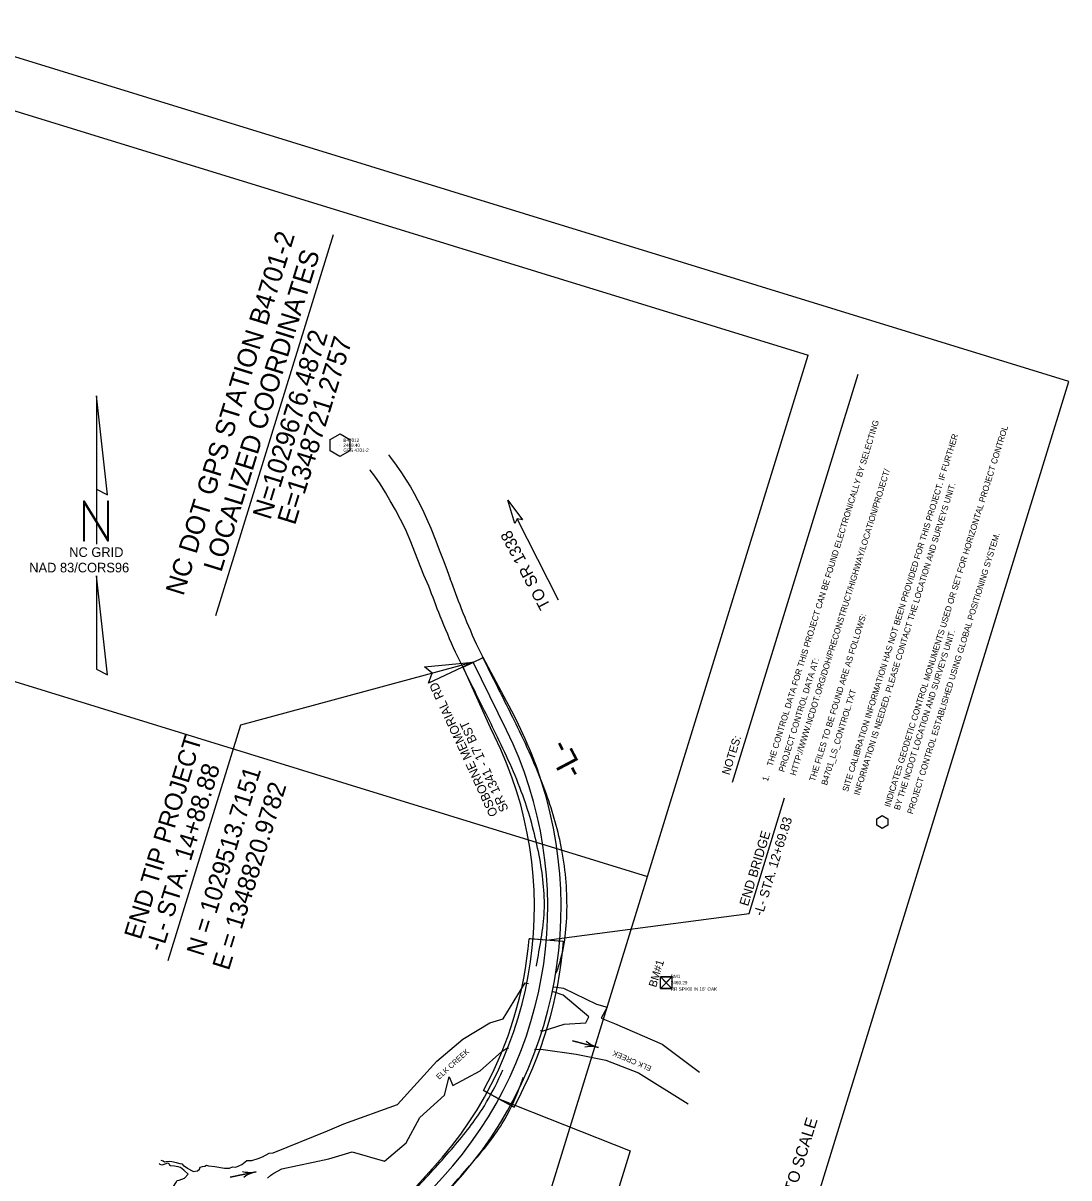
# Model space of a CAD drawing. Extents: x 1348011 to 1349268, y 1028333 to 1030014.
# Drawn here: x 1348484 to 1349268, y 1029127 to 1029993 of the extents above; entities that cross this region are included whole.
import ezdxf

# ---------------------------------------------------------------- set-up
doc = ezdxf.new("R2010")
doc.units = 0
for name, color, linetype in [('CTL Bench Mark CELL', 7, 'Continuous'), ('CTL Bench Mark Cogo Comment', 7, 'Continuous'), ('CTL Bench Mark Cogo Elevation', 7, 'Continuous'), ('CTL Bench Mark Cogo Number', 7, 'Continuous'), ('CTL Bench Mark Text', 7, 'Continuous'), ('CTL GPS Vertical CELL', 7, 'Continuous'), ('CTL GPS Vertical Cogo Comment', 7, 'Continuous'), ('CTL GPS Vertical Cogo Elevation', 7, 'Continuous'), ('CTL GPS Vertical Cogo Number', 7, 'Continuous'), ('CTL North Arrow NAD 83 NSRS 2007 CELL', 7, 'Continuous'), ('CTL Sheet Border CELL', 7, 'Continuous'), ('CTL Sheet Notes CELL', 7, 'Continuous'), ('Default', 7, 'Continuous'), ('Exist Hydro River Flow Arrow CELL', 7, 'Continuous'), ('Exist Hydro Stream or Body of Water', 7, 'Continuous'), ('Exist Hydro Stream or Body of Water Text', 7, 'Continuous'), ('Exist Roads EOP', 7, 'Continuous'), ('Prop Horizontal Alignment', 7, 'Continuous'), ('Prop Horizontal Alignment Station Label', 7, 'Continuous'), ('Prop Leader Line Light', 7, 'Continuous'), ('Prop Leader Line Medium', 7, 'Continuous'), ('Prop Roadway Bridge', 7, 'Continuous'), ('Prop Shade Medium', 7, 'Continuous'), ('Prop Terminator CELL', 7, 'Continuous'), ('Scratch_Level_3', 7, 'Continuous'), ('Sheet Data Field CELL', 7, 'Continuous'), ('Sheet Symbology CELL', 7, 'Continuous')]:
    doc.layers.add(name, color=color, linetype=linetype)

msp = doc.modelspace()

# ---------------------------------------------------------------- linework, layer by layer
at = {"layer": 'CTL Bench Mark CELL'}
msp.add_line((1348965.75, 1029273.43), (1348965.75, 1029273.43), dxfattribs=at)
msp.add_lwpolyline([(1348961.43, 1029277.74), (1348970.06, 1029277.74), (1348970.06, 1029269.11), (1348961.43, 1029269.11)], close=True, dxfattribs=at)
for points in [[(1348970.06, 1029277.74), (1348961.43, 1029269.11), (1348965.74, 1029273.42), (1348970.06, 1029269.11), (1348961.43, 1029277.74)], [(1348965.74, 1029273.42), (1348970.06, 1029277.74), (1348961.43, 1029277.74), (1348965.74, 1029273.42)], [(1348965.74, 1029273.42), (1348961.43, 1029269.11), (1348970.06, 1029269.11), (1348965.74, 1029273.42)]]:
    msp.add_lwpolyline(points, dxfattribs=at)
at = {"layer": 'CTL GPS Vertical CELL'}
for p, q in [((1348721.24, 1029676.49), (1348721.24, 1029676.49)), ((1349127.83, 1029393.95), (1349127.83, 1029393.95))]:
    msp.add_line(p, q, dxfattribs=at)
for points in [[(1348713.88, 1029680.76), (1348721.29, 1029684.89), (1348728.7, 1029680.81), (1348728.58, 1029672.32), (1348721.17, 1029668.02), (1348713.88, 1029672.15)], [(1349123.64, 1029396.37), (1349127.85, 1029398.72), (1349132.06, 1029396.41), (1349132, 1029391.58), (1349127.79, 1029389.14), (1349123.64, 1029391.49)]]:
    msp.add_lwpolyline(points, close=True, dxfattribs=at)
at = {"layer": 'CTL North Arrow NAD 83 NSRS 2007 CELL'}
msp.add_line((1348538.91, 1029608.7), (1348538.91, 1029608.7), dxfattribs=at)
for points in [[(1348538.73, 1029713.44), (1348538.73, 1029643.45), (1348546.98, 1029639.33)], [(1348528.86, 1029604.78), (1348529.68, 1029604.78), (1348529.68, 1029632.77), (1348546.98, 1029604.78), (1348547.8, 1029604.78), (1348547.8, 1029634.41), (1348546.98, 1029634.41), (1348546.98, 1029606.42), (1348529.68, 1029634.41), (1348528.86, 1029634.41)], [(1348538.73, 1029508.44), (1348546.98, 1029504.34), (1348538.73, 1029578.43)]]:
    msp.add_lwpolyline(points, close=True, dxfattribs=at)
msp.add_lwpolyline([(1348538.73, 1029643.45), (1348538.73, 1029602.29)], dxfattribs=at)
at = {"layer": 'CTL Sheet Border CELL'}
msp.add_lwpolyline([(1348395.15, 1029993.01), (1348011.26, 1028746.43), (1348883.85, 1028477.71), (1349267.74, 1029724.29)], close=True, dxfattribs=at)
at = {"layer": 'CTL Sheet Notes CELL'}
msp.add_line((1349015.42, 1029423.77), (1349109.8, 1029729.66), dxfattribs=at)
at = {"layer": 'Default'}
for p, q in [((1348813.47, 1029510.02), (1348828.47, 1029517.41)), ((1348834.1, 1029464.45), (1348813.47, 1029510.02)), ((1348852.05, 1029473.29), (1348828.47, 1029517.41)), ((1348855.06, 1029467.16), (1348852.05, 1029473.29)), ((1348837.12, 1029458.33), (1348834.1, 1029464.45)), ((1348775.79, 1029117.88), (1348790.71, 1029134.15))]:
    msp.add_line(p, q, dxfattribs=at)
for radius in [310, 290]:
    msp.add_arc((1348576.98, 1029330.16), radius, 317.47773, 26.22881, dxfattribs=at)
at = {"layer": 'Exist Hydro River Flow Arrow CELL'}
for p, q in [((1348905.32, 1029227.31), (1348905.32, 1029227.31)), ((1348648.55, 1029129.62), (1348648.55, 1029129.62))]:
    msp.add_line(p, q, dxfattribs=at)
for points in [[(1348905.87, 1029229.53), (1348907.51, 1029228.31), (1348909.27, 1029227.21), (1348911.14, 1029226.26), (1348913.05, 1029225.46), (1348915.02, 1029224.89), (1348895.61, 1029229.73), (1348915.02, 1029224.89), (1348913.01, 1029225.31), (1348910.95, 1029225.51), (1348908.86, 1029225.54), (1348906.79, 1029225.4), (1348904.76, 1029225.09)], [(1348648.07, 1029131.85), (1348650.08, 1029131.48), (1348652.14, 1029131.27), (1348654.24, 1029131.24), (1348656.31, 1029131.36), (1348658.33, 1029131.72), (1348638.78, 1029127.51), (1348658.33, 1029131.72), (1348656.34, 1029131.22), (1348654.4, 1029130.48), (1348652.51, 1029129.59), (1348650.71, 1029128.55), (1348649.03, 1029127.38)]]:
    msp.add_lwpolyline(points, dxfattribs=at)
at = {"layer": 'Exist Hydro Stream or Body of Water'}
for points in [[(1348671.04, 1029145.85), (1348711.91, 1029162.47), (1348724.23, 1029167.73), (1348764.36, 1029182.18), (1348793.73, 1029214.59), (1348813.44, 1029231.21), (1348833.67, 1029243.41), (1348843.53, 1029246.37), (1348860.07, 1029273.27), (1348862.58, 1029272.92)], [(1348871.41, 1029237.6), (1348872.86, 1029237.11), (1348889.42, 1029242.41), (1348905.56, 1029243.38), (1348907.78, 1029247.78), (1348888.56, 1029264.14), (1348881.39, 1029266.69), (1348880.38, 1029266.29)], [(1348881.62, 1029270.25), (1348888.82, 1029269.24), (1348913.56, 1029257.38), (1348921.57, 1029255.16), (1348917.15, 1029246.84), (1348926.96, 1029242.82), (1348962.79, 1029227.39), (1348990.8, 1029206.3)], [(1348677.73, 1029133.76), (1348712.96, 1029141.41), (1348730.43, 1029146.71), (1348754.5, 1029139.72), (1348770.92, 1029153.32), (1348781.06, 1029172.35), (1348799.58, 1029188.98), (1348803.07, 1029202.76), (1348805.79, 1029196.31), (1348826.35, 1029207.46), (1348842.47, 1029221.94), (1348846.45, 1029224.45), (1348847.5, 1029224.4)], [(1348867.03, 1029223.6), (1348873.62, 1029223.33), (1348898.36, 1029219.75), (1348920.53, 1029215.34), (1348945.09, 1029205.74), (1348982.2, 1029182.64)], [(1348659.88, 1029141.67), (1348663.08, 1029142.95), (1348668.16, 1029145.64)], [(1348668.16, 1029145.64), (1348671.04, 1029145.85)], [(1348607.36, 1029129.9), (1348604.2, 1029132.95), (1348601.62, 1029134.74), (1348599.8, 1029135.25), (1348598.38, 1029135.69), (1348597.2, 1029135.92), (1348594.23, 1029136.02), (1348593.83, 1029136.37), (1348593.33, 1029137.1), (1348593.05, 1029137.51), (1348592.71, 1029137.92), (1348591.76, 1029138), (1348590.55, 1029137.59), (1348589.28, 1029137.07), (1348587.79, 1029136.63), (1348586.54, 1029137.04), (1348585.68, 1029137.74)], [(1348611.1, 1029131.84), (1348607.01, 1029134), (1348604.42, 1029135.94), (1348603.11, 1029137.25), (1348601.52, 1029137.51), (1348598.68, 1029138.39), (1348595.23, 1029139.1), (1348593.3, 1029139.32), (1348590.8, 1029139.09), (1348589.74, 1029138.98), (1348588.76, 1029139.5), (1348587.26, 1029140.22)], [(1348611.1, 1029131.84), (1348614.45, 1029132.4), (1348615.95, 1029133.55), (1348616.53, 1029135.05), (1348618.24, 1029135.49), (1348620.03, 1029135.77), (1348621.23, 1029136.6), (1348622.59, 1029136.22), (1348627.39, 1029135.64), (1348634.69, 1029134.3), (1348638.31, 1029134.32), (1348640.69, 1029135.47), (1348643.26, 1029135.23), (1348647.66, 1029137.1), (1348651.28, 1029140), (1348655.2, 1029140.13), (1348659.88, 1029141.67)], [(1348596.35, 1029120.56), (1348598.13, 1029123.25), (1348599.17, 1029125.06), (1348600.62, 1029125.28), (1348604.69, 1029126.88), (1348607.36, 1029129.9)], [(1348666.96, 1029126.75), (1348669.41, 1029129.16), (1348671.69, 1029130.65), (1348677.73, 1029133.76)]]:
    msp.add_lwpolyline(points, dxfattribs=at)
at = {"layer": 'Exist Roads EOP'}
for p, q in [((1348843.08, 1029207.34), (1348843.41, 1029208.1)), ((1348858.38, 1029201.61), (1348858.75, 1029202.41))]:
    msp.add_line(p, q, dxfattribs=at)
for points in [[(1348757.58, 1029669.32), (1348759.23, 1029667.29), (1348763.43, 1029661.47), (1348767.37, 1029655.84), (1348770.81, 1029650.35), (1348774, 1029645.31), (1348776.86, 1029640.16), (1348779.54, 1029635.14), (1348781.9, 1029630.7), (1348784.11, 1029626.15), (1348786.07, 1029621.65), (1348789.36, 1029614.22), (1348792.6, 1029606.07), (1348796.18, 1029596.87), (1348796.67, 1029595.55)], [(1348787.85, 1029570.74), (1348784.22, 1029578.99), (1348777.31, 1029596.39), (1348774.32, 1029604.14), (1348770.36, 1029613.41), (1348766.73, 1029620.69), (1348762.8, 1029627.98), (1348758.96, 1029634.85), (1348755.29, 1029641.09), (1348751.31, 1029647.43), (1348747.35, 1029653.15), (1348743.79, 1029657.75), (1348743.62, 1029657.95)], [(1348796.67, 1029595.55), (1348798.99, 1029589.28), (1348801.58, 1029582.62), (1348803.95, 1029576.19)]]:
    msp.add_lwpolyline(points, dxfattribs=at)
for points in [[(1348819.76, 1029497.12), (1348807.96, 1029521.32), (1348796.41, 1029548.28), (1348787.85, 1029570.74)], [(1348835.36, 1029503.16), (1348823.68, 1029527.32), (1348812.34, 1029553.89), (1348803.95, 1029576.19)], [(1348883.28, 1029280.61), (1348883.52, 1029281.22), (1348891.35, 1029324.78), (1348887.59, 1029372.72), (1348875.98, 1029414.87), (1348854.37, 1029465.03), (1348835.36, 1029503.16)], [(1348868.46, 1029285.84), (1348868.57, 1029286.44), (1348874.38, 1029327), (1348870.51, 1029369.07), (1348859.35, 1029410.97), (1348839.31, 1029457.59), (1348819.76, 1029497.12)], [(1348777.13, 1029117.89), (1348804.82, 1029148.44), (1348827.72, 1029178.39), (1348840.41, 1029201.66), (1348843.08, 1029207.34)], [(1348790.41, 1029105.15), (1348818.4, 1029136.04), (1348842.84, 1029167.86), (1348855.87, 1029194.81), (1348858.38, 1029201.61)]]:
    msp.add_spline(points, degree=3, dxfattribs=at)
at = {"layer": 'Prop Horizontal Alignment'}
for p, q in [((1348846.09, 1029462.75), (1348820.98, 1029513.72)), ((1348749.37, 1029074.27), (1348798.08, 1029127.4))]:
    msp.add_line(p, q, dxfattribs=at)
msp.add_arc((1348576.98, 1029330.16), 300, 317.47773, 26.22881, dxfattribs=at)
at = {"layer": 'Prop Horizontal Alignment Station Label'}
msp.add_line((1348716.15, 1029834.23), (1348627.86, 1029548.54), dxfattribs=at)
at = {"layer": 'Prop Leader Line Medium'}
for p, q in [((1348820.98, 1029513.72), (1348646.58, 1029466.47)), ((1348646.58, 1029466.47), (1348592.15, 1029289.72)), ((1349027.91, 1029325.42), (1349054.57, 1029411.99)), ((1348875.95, 1029305.29), (1349027.91, 1029325.42)), ((1348840.31, 1029186.43), (1348938.84, 1029147.29)), ((1348938.84, 1029147.29), (1348911.11, 1029057.24))]:
    msp.add_line(p, q, dxfattribs=at)
at = {"layer": 'Prop Roadway Bridge'}
for p, q in [((1348888.9, 1029304.22), (1348862.99, 1029306.37)), ((1348851.72, 1029180.2), (1348828.89, 1029192.65)), ((1348829.77, 1029192.17), (1348850.84, 1029180.67))]:
    msp.add_line(p, q, dxfattribs=at)
for radius in [287, 313]:
    msp.add_arc((1348576.98, 1029330.16), radius, 331.37242, 355.24567, dxfattribs=at)
at = {"layer": 'Prop Shade Medium'}
for p, q in [((1348863.99, 1029306.29), (1348862.99, 1029306.37)), ((1348887.91, 1029304.3), (1348863.99, 1029306.29)), ((1348828.89, 1029192.65), (1348851.72, 1029180.2))]:
    msp.add_line(p, q, dxfattribs=at)
for radius in [287, 313]:
    msp.add_arc((1348576.98, 1029330.16), radius, 331.37242, 355.24567, dxfattribs=at)
at = {"layer": 'Prop Terminator CELL'}
for points in [[(1348852.35, 1029617.86), (1348846.99, 1029635.32), (1348858.02, 1029620.61), (1348854.12, 1029621.22)], [(1348784.6, 1029510.39), (1348820.98, 1029513.72), (1348787.67, 1029498.16), (1348790.45, 1029505.54)]]:
    msp.add_lwpolyline(points, close=True, dxfattribs=at)
at = {"layer": 'Scratch_Level_3'}
for p, q in [((1348428.33, 1029942.38), (1349072.16, 1029744.11)), ((1348951.78, 1029353.2), (1349072.16, 1029744.11)), ((1348307.95, 1029551.47), (1348951.78, 1029353.2)), ((1348831.4, 1028962.29), (1348951.78, 1029353.2))]:
    msp.add_line(p, q, dxfattribs=at)
at = {"layer": 'Sheet Symbology CELL'}
msp.add_line((1348885.06, 1029560.27), (1348854.08, 1029621.19), dxfattribs=at)

# ---------------------------------------------------------------- texts
at = {"layer": 'CTL Bench Mark Cogo Comment'}
msp.add_text('RR SPIKE IN 16" OAK', height=2.5, dxfattribs=at).set_placement((1348969.25, 1029267.43))
at = {"layer": 'CTL Bench Mark Cogo Elevation'}
msp.add_text('2469.29', height=2.5, dxfattribs=at).set_placement((1348969.25, 1029272.18))
at = {"layer": 'CTL Bench Mark Cogo Number'}
msp.add_text('BM1', height=2.5, dxfattribs=at).set_placement((1348969.25, 1029276.93))
at = {"layer": 'CTL Bench Mark Text'}
msp.add_text('BM#1', height=6, rotation=72.88344, dxfattribs=at).set_placement((1348958.19, 1029269.54))
at = {"layer": 'CTL GPS Vertical Cogo Comment'}
msp.add_text('GPS 4701-2', height=2.5, dxfattribs=at).set_placement((1348723.78, 1029671.49))
at = {"layer": 'CTL GPS Vertical Cogo Elevation'}
msp.add_text('2489.40', height=2.5, dxfattribs=at).set_placement((1348723.78, 1029675.24))
at = {"layer": 'CTL GPS Vertical Cogo Number'}
msp.add_text('B47012', height=2.5, dxfattribs=at).set_placement((1348723.78, 1029678.99))
at = {"layer": 'CTL North Arrow NAD 83 NSRS 2007 CELL'}
for s, p in [('NC GRID', (1348518.24, 1029592.69)), (' NAD 83/CORS96', (1348485.61, 1029581.12))]:
    msp.add_text(s, height=7.2, dxfattribs=at).set_placement(p)
at = {"layer": 'CTL Sheet Border CELL'}
msp.add_text('NOTE: DRAWING NOT TO SCALE', height=8.6957, rotation=72.77817, dxfattribs=at).set_placement((1349025.09, 1028995.35))
at = {"layer": 'CTL Sheet Notes CELL'}
for s, height, rotation, p in [('1.    THE CONTROL DATA FOR THIS PROJECT CAN BE FOUND ELECTRONICALLY BY SELECTING', 4.552, 72.85294, (1349042.02, 1029424.03)), ('SITE CALIBRATION INFORMATION HAS NOT BEEN PROVIDED FOR THIS PROJECT. IF FURTHER', 4.552, 72.85294, (1349102.09, 1029416.29)), ('INDICATES GEODETIC CONTROL MONUMENTS USED OR SET FOR HORIZONTAL PROJECT CONTROL', 4.552, 72.74769, (1349133.56, 1029404.82)), ('HTTP://WWW.NCDOT.ORG/DOH/PRECONSTRUCT/HIGHWAY/LOCATION/PROJECT/', 4.552, 72.85294, (1349062.89, 1029428.38)), ('INFORMATION IS NEEDED, PLEASE CONTACT THE LOCATION AND SURVEYS UNIT.', 4.552, 72.85294, (1349110.65, 1029413.65)), ('PROJECT CONTROL ESTABLISHED USING GLOBAL POSITIONING SYSTEM.', 4.552, 72.74769, (1349150.68, 1029399.5)), ('THE FILES TO BE FOUND ARE AS FOLLOWS:', 4.552, 72.85294, (1349077.26, 1029423.95)), ('BY THE NCDOT LOCATION AND SURVEYS UNIT.', 4.552, 72.74769, (1349140.79, 1029402.55)), ('PROJECT CONTROL DATA AT:', 4.552, 72.85294, (1349054.27, 1029431.04)), ('B4701_LS_CONTROL.TXT', 4.552, 72.85294, (1349086.3, 1029421.16)), ('NOTES:', 6.069, 72.74769, (1349013.18, 1029428.79))]:
    msp.add_text(s, height=height, rotation=rotation, dxfattribs=at).set_placement(p)
at = {"layer": 'Default'}
for s, p in [('OSBORNE MEMORIAL RD', (1348839.82, 1029399.77)), ("SR 1341 - 17' BST", (1348847.74, 1029403.42))]:
    msp.add_text(s, height=6.6501, rotation=114.71559, dxfattribs=at).set_placement(p)
at = {"layer": 'Exist Hydro Stream or Body of Water Text'}
for rotation, p in [(41.92217, (1348795.5, 1029200.57)), (156.69533, (1348955.18, 1029210.54))]:
    msp.add_text('ELK CREEK', height=4, rotation=rotation, dxfattribs=at).set_placement(p)
at = {"layer": 'Prop Horizontal Alignment Station Label'}
for s, p in [('NC DOT GPS STATION B4701-2', (1348603.8, 1029562.96)), ('LOCALIZED COORDINATES', (1348632.2, 1029580.69)), ('N=1029676.4872', (1348669.02, 1029619.94)), ('E=1348721.2757', (1348687.48, 1029616.01))]:
    msp.add_text(s, height=14.25, rotation=72.83038, dxfattribs=at).set_placement(p)
at = {"layer": 'Prop Leader Line Light'}
for s, height, rotation, p in [('END TIP PROJECT', 13.3, 73.07402, (1348571.83, 1029305.13)), ('-L- STA. 14+88.88', 13.3, 72.70897, (1348588.13, 1029296.03)), ('N = 1029513.7151 ', 13.3, 72.70897, (1348618.59, 1029292.64)), ('E = 1348820.9782 ', 13.3, 72.70897, (1348637.89, 1029282.03)), ('-L- STA. 12+69.83', 7, 73.07402, (1349038.03, 1029323.03))]:
    msp.add_text(s, height=height, rotation=rotation, dxfattribs=at).set_placement(p)
at = {"layer": 'Prop Leader Line Medium'}
msp.add_text('END BRIDGE', height=7, rotation=73.07402, dxfattribs=at).set_placement((1349027.2, 1029330.39))
at = {"layer": 'Sheet Data Field CELL'}
for s, height, p in [('TO SR 1338', 8.75, (1348879.32, 1029555.98)), ('-L-', 17.5, (1348904.38, 1029431.94))]:
    msp.add_text(s, height=height, rotation=117.89209, dxfattribs=at).set_placement(p)

doc.saveas('drawing.dxf')
